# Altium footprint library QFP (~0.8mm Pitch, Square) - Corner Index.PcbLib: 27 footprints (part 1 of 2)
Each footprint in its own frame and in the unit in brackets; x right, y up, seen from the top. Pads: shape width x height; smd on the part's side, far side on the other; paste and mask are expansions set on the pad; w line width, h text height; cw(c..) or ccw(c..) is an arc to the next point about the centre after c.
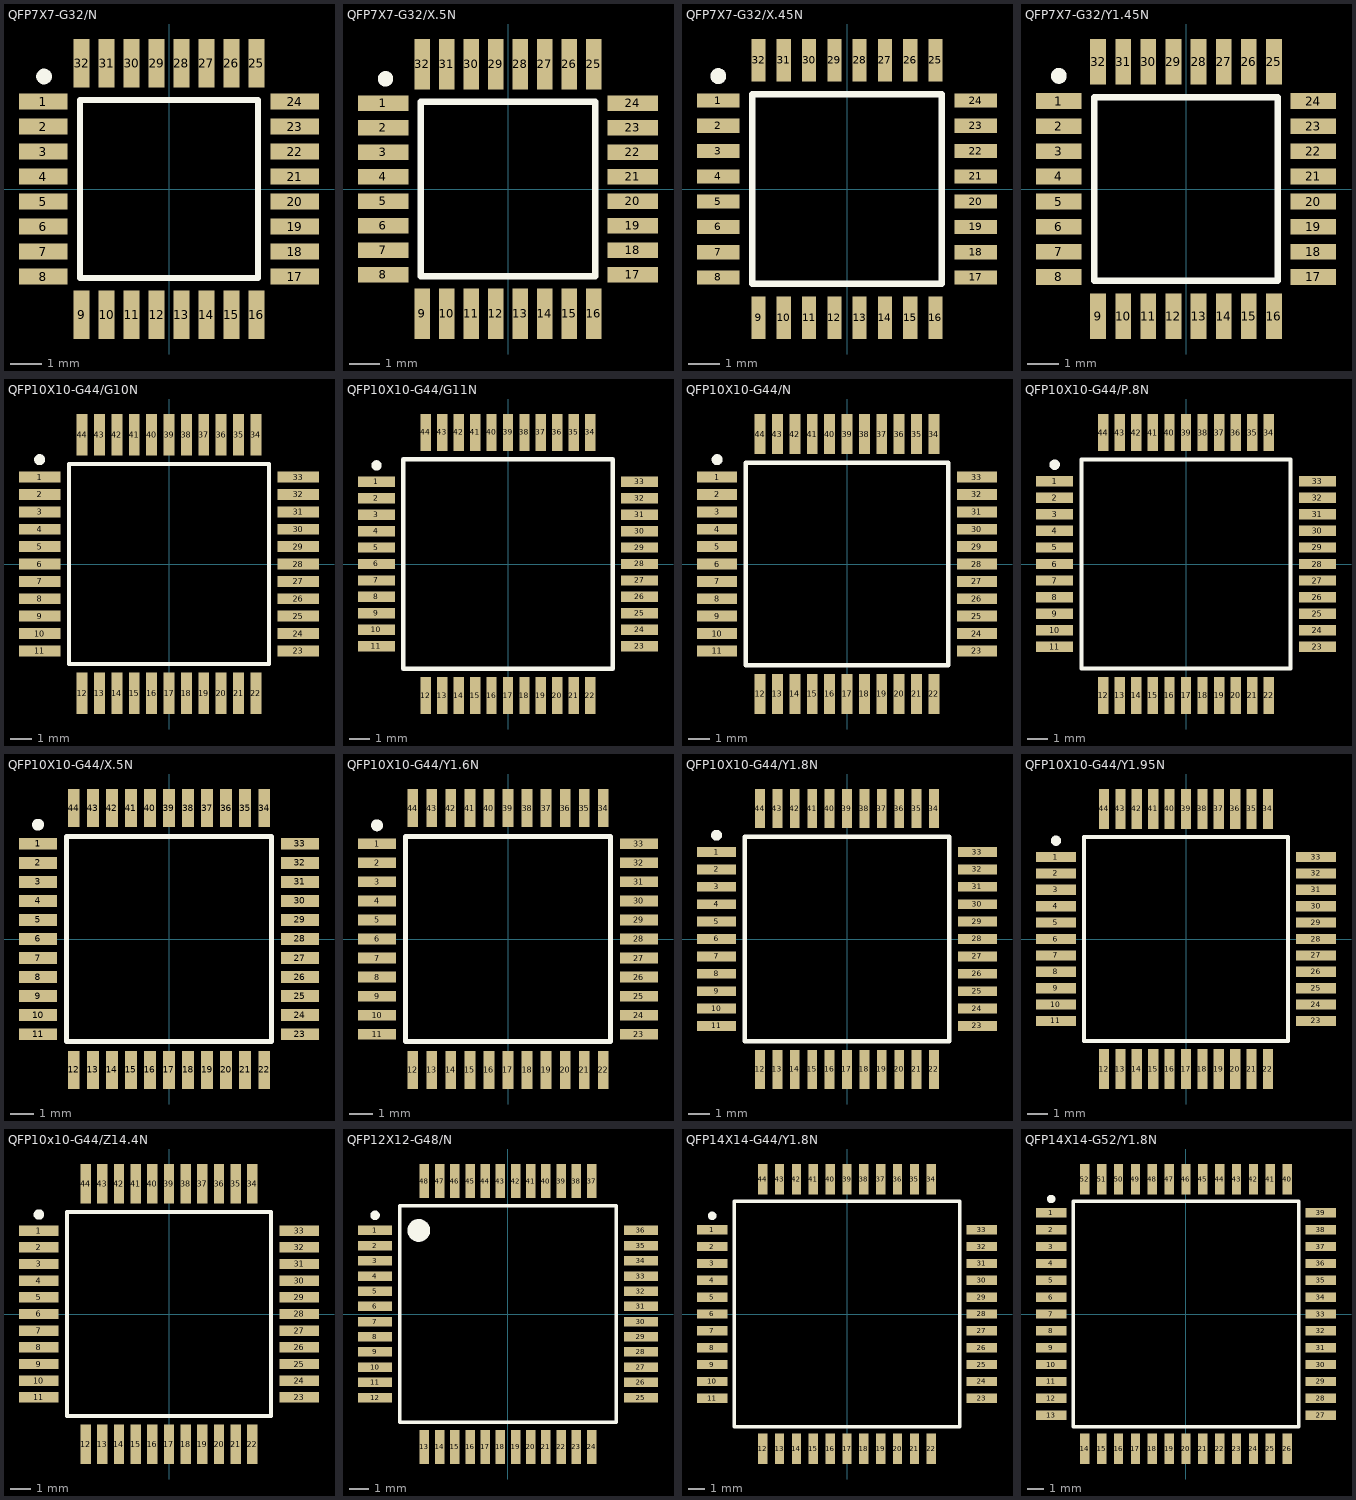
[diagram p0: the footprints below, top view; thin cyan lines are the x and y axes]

## QFP7X7-G32/N [mm]
pads (32):
  rect 1.55x0.5 smd: 1(-4.025,2.8) 2(-4.025,2) 3(-4.025,1.2) 4(-4.025,0.4) 5(-4.025,-0.4) 6(-4.025,-1.2) 7(-4.025,-2) 8(-4.025,-2.8) 17(4.025,-2.8) 18(4.025,-2) 19(4.025,-1.2) 20(4.025,-0.4) 21(4.025,0.4) 22(4.025,1.2) 23(4.025,2) 24(4.025,2.8)
  rect 0.5x1.55 smd: 9(-2.8,-4.025) 10(-2,-4.025) 11(-1.2,-4.025) 12(-0.4,-4.025) 13(0.4,-4.025) 14(1.2,-4.025) 15(2,-4.025) 16(2.8,-4.025) 25(2.8,4.025) 26(2,4.025) 27(1.2,4.025) 28(0.4,4.025) 29(-0.4,4.025) 30(-1.2,4.025) 31(-2,4.025) 32(-2.8,4.025)
Top Overlay:
  circle w0.25: c-4,3.6 r0.125
  lines w0.2: -2.85,-2.85 -2.85,2.85 2.85,2.85 2.85,-2.85 -2.85,-2.85

## QFP7X7-G32/X.5N [mm]
pads (32):
  rect 1.65x0.5 smd: 1(-4.075,2.8) 2(-4.075,2) 3(-4.075,1.2) 4(-4.075,0.4) 5(-4.075,-0.4) 6(-4.075,-1.2) 7(-4.075,-2) 8(-4.075,-2.8) 17(4.075,-2.8) 18(4.075,-2) 19(4.075,-1.2) 20(4.075,-0.4) 21(4.075,0.4) 22(4.075,1.2) 23(4.075,2) 24(4.075,2.8)
  rect 0.5x1.65 smd: 9(-2.8,-4.075) 10(-2,-4.075) 11(-1.2,-4.075) 12(-0.4,-4.075) 13(0.4,-4.075) 14(1.2,-4.075) 15(2,-4.075) 16(2.8,-4.075) 25(2.8,4.075) 26(2,4.075) 27(1.2,4.075) 28(0.4,4.075) 29(-0.4,4.075) 30(-1.2,4.075) 31(-2,4.075) 32(-2.8,4.075)
Top Overlay:
  circle w0.25: c-4,3.6 r0.125
  lines w0.2: -2.85,-2.85 -2.85,2.85 2.85,2.85 2.85,-2.85 -2.85,-2.85

## QFP7X7-G32/X.45N [mm]
pads (32):
  rect 1.35x0.45 smd: 1(-4.075,2.8) 2(-4.075,2) 3(-4.075,1.2) 4(-4.075,0.4) 5(-4.075,-0.4) 6(-4.075,-1.2) 7(-4.075,-2) 8(-4.075,-2.8) 17(4.075,-2.8) 18(4.075,-2) 19(4.075,-1.2) 20(4.075,-0.4) 21(4.075,0.4) 22(4.075,1.2) 23(4.075,2) 24(4.075,2.8)
  rect 0.45x1.35 smd: 9(-2.8,-4.075) 10(-2,-4.075) 11(-1.2,-4.075) 12(-0.4,-4.075) 13(0.4,-4.075) 14(1.2,-4.075) 15(2,-4.075) 16(2.8,-4.075) 25(2.8,4.075) 26(2,4.075) 27(1.2,4.075) 28(0.4,4.075) 29(-0.4,4.075) 30(-1.2,4.075) 31(-2,4.075) 32(-2.8,4.075)
Top Overlay:
  circle w0.25: c-4.075,3.575 r0.125
  lines w0.2: -3,-3 3,-3 3,3 -3,3 -3,-3

## QFP7X7-G32/Y1.45N [mm]
pads (32):
  rect 1.45x0.5 smd: 1(-4.05,2.8) 2(-4.05,2) 3(-4.05,1.2) 4(-4.05,0.4) 5(-4.05,-0.4) 6(-4.05,-1.2) 7(-4.05,-2) 8(-4.05,-2.8) 17(4.05,-2.8) 18(4.05,-2) 19(4.05,-1.2) 20(4.05,-0.4) 21(4.05,0.4) 22(4.05,1.2) 23(4.05,2) 24(4.05,2.8)
  rect 0.5x1.45 smd: 9(-2.8,-4.05) 10(-2,-4.05) 11(-1.2,-4.05) 12(-0.4,-4.05) 13(0.4,-4.05) 14(1.2,-4.05) 15(2,-4.05) 16(2.8,-4.05) 25(2.8,4.05) 26(2,4.05) 27(1.2,4.05) 28(0.4,4.05) 29(-0.4,4.05) 30(-1.2,4.05) 31(-2,4.05) 32(-2.8,4.05)
Top Overlay:
  circle w0.25: c-4.05,3.6 r0.125
  lines w0.2: -2.925,-2.925 -2.925,2.925 2.925,2.925 2.925,-2.925 -2.925,-2.925

## QFP10X10-G44/G10N [mm]
pads (44):
  rect 1.9x0.5 smd: 1(-5.95,4) 2(-5.95,3.2) 3(-5.95,2.4) 4(-5.95,1.6) 5(-5.95,0.8) 6(-5.95,0) 7(-5.95,-0.8) 8(-5.95,-1.6) 9(-5.95,-2.4) 10(-5.95,-3.2) 11(-5.95,-4) 23(5.95,-4) 24(5.95,-3.2) 25(5.95,-2.4) 26(5.95,-1.6) 27(5.95,-0.8) 28(5.95,0) 29(5.95,0.8) 30(5.95,1.6) 31(5.95,2.4) 32(5.95,3.2) 33(5.95,4)
  rect 0.5x1.9 smd: 12(-4,-5.95) 13(-3.2,-5.95) 14(-2.4,-5.95) 15(-1.6,-5.95) 16(-0.8,-5.95) 17(0,-5.95) 18(0.8,-5.95) 19(1.6,-5.95) 20(2.4,-5.95) 21(3.2,-5.95) 22(4,-5.95) 34(4,5.95) 35(3.2,5.95) 36(2.4,5.95) 37(1.6,5.95) 38(0.8,5.95) 39(0,5.95) 40(-0.8,5.95) 41(-1.6,5.95) 42(-2.4,5.95) 43(-3.2,5.95) 44(-4,5.95)
Top Overlay:
  circle w0.25: c-5.95,4.8 r0.125
  lines w0.2: -4.6,-4.6 4.6,-4.6 4.6,4.6 -4.6,4.6 -4.6,-4.6

## QFP10X10-G44/G11N [mm]
pads (44):
  rect 1.8x0.5 smd: 1(-6.4,4) 2(-6.4,3.2) 3(-6.4,2.4) 4(-6.4,1.6) 5(-6.4,0.8) 6(-6.4,0) 7(-6.4,-0.8) 8(-6.4,-1.6) 9(-6.4,-2.4) 10(-6.4,-3.2) 11(-6.4,-4) 23(6.4,-4) 24(6.4,-3.2) 25(6.4,-2.4) 26(6.4,-1.6) 27(6.4,-0.8) 28(6.4,0) 29(6.4,0.8) 30(6.4,1.6) 31(6.4,2.4) 32(6.4,3.2) 33(6.4,4)
  rect 0.5x1.8 smd: 12(-4,-6.4) 13(-3.2,-6.4) 14(-2.4,-6.4) 15(-1.6,-6.4) 16(-0.8,-6.4) 17(0,-6.4) 18(0.8,-6.4) 19(1.6,-6.4) 20(2.4,-6.4) 21(3.2,-6.4) 22(4,-6.4) 34(4,6.4) 35(3.2,6.4) 36(2.4,6.4) 37(1.6,6.4) 38(0.8,6.4) 39(0,6.4) 40(-0.8,6.4) 41(-1.6,6.4) 42(-2.4,6.4) 43(-3.2,6.4) 44(-4,6.4)
Top Overlay:
  circle w0.25: c-6.4,4.8 r0.125
  lines w0.2: -5.1,-5.1 5.1,-5.1 5.1,5.1 -5.1,5.1 -5.1,-5.1

## QFP10X10-G44/N [mm]
pads (44):
  rect 1.85x0.5 smd: 1(-5.975,4) 2(-5.975,3.2) 3(-5.975,2.4) 4(-5.975,1.6) 5(-5.975,0.8) 6(-5.975,0) 7(-5.975,-0.8) 8(-5.975,-1.6) 9(-5.975,-2.4) 10(-5.975,-3.2) 11(-5.975,-4) 23(5.975,-4) 24(5.975,-3.2) 25(5.975,-2.4) 26(5.975,-1.6) 27(5.975,-0.8) 28(5.975,0) 29(5.975,0.8) 30(5.975,1.6) 31(5.975,2.4) 32(5.975,3.2) 33(5.975,4)
  rect 0.5x1.85 smd: 12(-4,-5.975) 13(-3.2,-5.975) 14(-2.4,-5.975) 15(-1.6,-5.975) 16(-0.8,-5.975) 17(0,-5.975) 18(0.8,-5.975) 19(1.6,-5.975) 20(2.4,-5.975) 21(3.2,-5.975) 22(4,-5.975) 34(4,5.975) 35(3.2,5.975) 36(2.4,5.975) 37(1.6,5.975) 38(0.8,5.975) 39(0,5.975) 40(-0.8,5.975) 41(-1.6,5.975) 42(-2.4,5.975) 43(-3.2,5.975) 44(-4,5.975)
Top Overlay:
  circle w0.25: c-5.975,4.8 r0.125
  lines w0.2: -4.65,-4.65 4.65,-4.65 4.65,4.65 -4.65,4.65 -4.65,-4.65

## QFP10X10-G44/P.8N [mm]
pads (44):
  rect 1.8x0.5 smd: 1(-6.35,4) 2(-6.35,3.2) 3(-6.35,2.4) 4(-6.35,1.6) 5(-6.35,0.8) 6(-6.35,0) 7(-6.35,-0.8) 8(-6.35,-1.6) 9(-6.35,-2.4) 10(-6.35,-3.2) 11(-6.35,-4) 23(6.35,-4) 24(6.35,-3.2) 25(6.35,-2.4) 26(6.35,-1.6) 27(6.35,-0.8) 28(6.35,0) 29(6.35,0.8) 30(6.35,1.6) 31(6.35,2.4) 32(6.35,3.2) 33(6.35,4)
  rect 0.5x1.8 smd: 12(-4,-6.35) 13(-3.2,-6.35) 14(-2.4,-6.35) 15(-1.6,-6.35) 16(-0.8,-6.35) 17(0,-6.35) 18(0.8,-6.35) 19(1.6,-6.35) 20(2.4,-6.35) 21(3.2,-6.35) 22(4,-6.35) 34(4,6.35) 35(3.2,6.35) 36(2.4,6.35) 37(1.6,6.35) 38(0.8,6.35) 39(0,6.35) 40(-0.8,6.35) 41(-1.6,6.35) 42(-2.4,6.35) 43(-3.2,6.35) 44(-4,6.35)
Top Overlay:
  circle w0.25: c-6.35,4.8 r0.125
  lines w0.2: -5.05,-5.05 -5.05,5.05 5.05,5.05 5.05,-5.05 -5.05,-5.05

## QFP10X10-G44/X.5N [mm]
pads (44):
  rect 1.6x0.5 smd: 1(-5.5,4) 2(-5.5,3.2) 3(-5.5,2.4) 4(-5.5,1.6) 5(-5.5,0.8) 6(-5.5,0) 7(-5.5,-0.8) 8(-5.5,-1.6) 9(-5.5,-2.4) 10(-5.5,-3.2) 11(-5.5,-4) 23(5.5,-4) 24(5.5,-3.2) 25(5.5,-2.4) 26(5.5,-1.6) 27(5.5,-0.8) 28(5.5,0) 29(5.5,0.8) 30(5.5,1.6) 31(5.5,2.4) 32(5.5,3.2) 33(5.5,4)
  rect 0.5x1.6 smd: 12(-4,-5.5) 13(-3.2,-5.5) 14(-2.4,-5.5) 15(-1.6,-5.5) 16(-0.8,-5.5) 17(0,-5.5) 18(0.8,-5.5) 19(1.6,-5.5) 20(2.4,-5.5) 21(3.2,-5.5) 22(4,-5.5) 34(4,5.5) 35(3.2,5.5) 36(2.4,5.5) 37(1.6,5.5) 38(0.8,5.5) 39(0,5.5) 40(-0.8,5.5) 41(-1.6,5.5) 42(-2.4,5.5) 43(-3.2,5.5) 44(-4,5.5)
Top Overlay:
  circle w0.25: c-5.5,4.8 r0.125
  lines w0.2: -4.3,-4.3 4.3,-4.3 4.3,4.3 -4.3,4.3 -4.3,-4.3

## QFP10X10-G44/Y1.6N [mm]
pads (44):
  rect 1.6x0.45 smd: 1(-5.5,4) 2(-5.5,3.2) 3(-5.5,2.4) 4(-5.5,1.6) 5(-5.5,0.8) 6(-5.5,0) 7(-5.5,-0.8) 8(-5.5,-1.6) 9(-5.5,-2.4) 10(-5.5,-3.2) 11(-5.5,-4) 23(5.5,-4) 24(5.5,-3.2) 25(5.5,-2.4) 26(5.5,-1.6) 27(5.5,-0.8) 28(5.5,0) 29(5.5,0.8) 30(5.5,1.6) 31(5.5,2.4) 32(5.5,3.2) 33(5.5,4)
  rect 0.45x1.6 smd: 12(-4,-5.5) 13(-3.2,-5.5) 14(-2.4,-5.5) 15(-1.6,-5.5) 16(-0.8,-5.5) 17(0,-5.5) 18(0.8,-5.5) 19(1.6,-5.5) 20(2.4,-5.5) 21(3.2,-5.5) 22(4,-5.5) 34(4,5.5) 35(3.2,5.5) 36(2.4,5.5) 37(1.6,5.5) 38(0.8,5.5) 39(0,5.5) 40(-0.8,5.5) 41(-1.6,5.5) 42(-2.4,5.5) 43(-3.2,5.5) 44(-4,5.5)
Top Overlay:
  circle w0.25: c-5.5,4.775 r0.125
  lines w0.2: -4.3,-4.3 -4.3,4.3 4.3,4.3 4.3,-4.3 -4.3,-4.3

## QFP10X10-G44/Y1.8N [mm]
pads (44):
  rect 1.8x0.45 smd: 1(-6,4) 2(-6,3.2) 3(-6,2.4) 4(-6,1.6) 5(-6,0.8) 6(-6,0) 7(-6,-0.8) 8(-6,-1.6) 9(-6,-2.4) 10(-6,-3.2) 11(-6,-4) 23(6,-4) 24(6,-3.2) 25(6,-2.4) 26(6,-1.6) 27(6,-0.8) 28(6,0) 29(6,0.8) 30(6,1.6) 31(6,2.4) 32(6,3.2) 33(6,4)
  rect 0.45x1.8 smd: 12(-4,-6) 13(-3.2,-6) 14(-2.4,-6) 15(-1.6,-6) 16(-0.8,-6) 17(0,-6) 18(0.8,-6) 19(1.6,-6) 20(2.4,-6) 21(3.2,-6) 22(4,-6) 34(4,6) 35(3.2,6) 36(2.4,6) 37(1.6,6) 38(0.8,6) 39(0,6) 40(-0.8,6) 41(-1.6,6) 42(-2.4,6) 43(-3.2,6) 44(-4,6)
Top Overlay:
  circle w0.25: c-6,4.775 r0.125
  lines w0.2: -4.7,-4.7 4.7,-4.7 4.7,4.7 -4.7,4.7 -4.7,-4.7

## QFP10X10-G44/Y1.95N [mm]
pads (44):
  rect 1.95x0.5 smd: 1(-6.35,4) 2(-6.35,3.2) 3(-6.35,2.4) 4(-6.35,1.6) 5(-6.35,0.8) 6(-6.35,0) 7(-6.35,-0.8) 8(-6.35,-1.6) 9(-6.35,-2.4) 10(-6.35,-3.2) 11(-6.35,-4) 23(6.35,-4) 24(6.35,-3.2) 25(6.35,-2.4) 26(6.35,-1.6) 27(6.35,-0.8) 28(6.35,0) 29(6.35,0.8) 30(6.35,1.6) 31(6.35,2.4) 32(6.35,3.2) 33(6.35,4)
  rect 0.5x1.95 smd: 12(-4,-6.35) 13(-3.2,-6.35) 14(-2.4,-6.35) 15(-1.6,-6.35) 16(-0.8,-6.35) 17(0,-6.35) 18(0.8,-6.35) 19(1.6,-6.35) 20(2.4,-6.35) 21(3.2,-6.35) 22(4,-6.35) 34(4,6.35) 35(3.2,6.35) 36(2.4,6.35) 37(1.6,6.35) 38(0.8,6.35) 39(0,6.35) 40(-0.8,6.35) 41(-1.6,6.35) 42(-2.4,6.35) 43(-3.2,6.35) 44(-4,6.35)
Top Overlay:
  circle w0.25: c-6.35,4.8 r0.125
  lines w0.2: -4.975,-4.975 4.975,-4.975 4.975,4.975 -4.975,4.975 -4.975,-4.975

## QFP10x10-G44/Z14.4N [mm]
pads (44):
  rect 1.9x0.5 smd: 1(-6.25,4) 2(-6.25,3.2) 3(-6.25,2.4) 4(-6.25,1.6) 5(-6.25,0.8) 6(-6.25,0) 7(-6.25,-0.8) 8(-6.25,-1.6) 9(-6.25,-2.4) 10(-6.25,-3.2) 11(-6.25,-4) 23(6.25,-4) 24(6.25,-3.2) 25(6.25,-2.4) 26(6.25,-1.6) 27(6.25,-0.8) 28(6.25,0) 29(6.25,0.8) 30(6.25,1.6) 31(6.25,2.4) 32(6.25,3.2) 33(6.25,4)
  rect 0.5x1.9 smd: 12(-4,-6.25) 13(-3.2,-6.25) 14(-2.4,-6.25) 15(-1.6,-6.25) 16(-0.8,-6.25) 17(0,-6.25) 18(0.8,-6.25) 19(1.6,-6.25) 20(2.4,-6.25) 21(3.2,-6.25) 22(4,-6.25) 34(4,6.25) 35(3.2,6.25) 36(2.4,6.25) 37(1.6,6.25) 38(0.8,6.25) 39(0,6.25) 40(-0.8,6.25) 41(-1.6,6.25) 42(-2.4,6.25) 43(-3.2,6.25) 44(-4,6.25)
Top Overlay:
  circle w0.25: c-6.25,4.775 r0.125
  lines w0.2: -4.9,-4.9 -4.9,4.9 4.9,4.9 4.9,-4.9 -4.9,-4.9

## QFP12X12-G48/N [mm]
pads (48):
  rect 1.8x0.5 smd: 1(-7,4.4) 2(-7,3.6) 3(-7,2.8) 4(-7,2) 5(-7,1.2) 6(-7,0.4) 7(-7,-0.4) 8(-7,-1.2) 9(-7,-2) 10(-7,-2.8) 11(-7,-3.6) 12(-7,-4.4) 25(7,-4.4) 26(7,-3.6) 27(7,-2.8) 28(7,-2) 29(7,-1.2) 30(7,-0.4) 31(7,0.4) 32(7,1.2) 33(7,2) 34(7,2.8) 35(7,3.6) 36(7,4.4)
  rect 0.5x1.8 smd: 13(-4.4,-7) 14(-3.6,-7) 15(-2.8,-7) 16(-2,-7) 17(-1.2,-7) 18(-0.4,-7) 19(0.4,-7) 20(1.2,-7) 21(2,-7) 22(2.8,-7) 23(3.6,-7) 24(4.4,-7) 37(4.4,7) 38(3.6,7) 39(2.8,7) 40(2,7) 41(1.2,7) 42(0.4,7) 43(-0.4,7) 44(-1.2,7) 45(-2,7) 46(-2.8,7) 47(-3.6,7) 48(-4.4,7)
Top Overlay:
  circle w0.25: c-7,5.2 r0.125
  circle w0.6: c-4.7,4.4 r0.3
  lines w0.2: -5.7,-5.7 5.7,-5.7 5.7,5.7 -5.7,5.7 -5.7,-5.7

## QFP14X14-G44/Y1.8N [mm]
pads (44):
  rect 1.8x0.55 smd: 1(-8,5) 2(-8,4) 3(-8,3) 4(-8,2) 5(-8,1) 6(-8,0) 7(-8,-1) 8(-8,-2) 9(-8,-3) 10(-8,-4) 11(-8,-5) 23(8,-5) 24(8,-4) 25(8,-3) 26(8,-2) 27(8,-1) 28(8,0) 29(8,1) 30(8,2) 31(8,3) 32(8,4) 33(8,5)
  rect 0.55x1.8 smd: 12(-5,-8) 13(-4,-8) 14(-3,-8) 15(-2,-8) 16(-1,-8) 17(0,-8) 18(1,-8) 19(2,-8) 20(3,-8) 21(4,-8) 22(5,-8) 34(5,8) 35(4,8) 36(3,8) 37(2,8) 38(1,8) 39(0,8) 40(-1,8) 41(-2,8) 42(-3,8) 43(-4,8) 44(-5,8)
Top Overlay:
  circle w0.25: c-8,5.825 r0.125
  lines w0.2: -6.7,-6.7 6.7,-6.7 6.7,6.7 -6.7,6.7 -6.7,-6.7

## QFP14X14-G52/Y1.8N [mm]
pads (52):
  rect 1.8x0.55 smd: 1(-8,6) 2(-8,5) 3(-8,4) 4(-8,3) 5(-8,2) 6(-8,1) 7(-8,0) 8(-8,-1) 9(-8,-2) 10(-8,-3) 11(-8,-4) 12(-8,-5) 13(-8,-6) 27(8,-6) 28(8,-5) 29(8,-4) 30(8,-3) 31(8,-2) 32(8,-1) 33(8,0) 34(8,1) 35(8,2) 36(8,3) 37(8,4) 38(8,5) 39(8,6)
  rect 0.55x1.8 smd: 14(-6,-8) 15(-5,-8) 16(-4,-8) 17(-3,-8) 18(-2,-8) 19(-1,-8) 20(0,-8) 21(1,-8) 22(2,-8) 23(3,-8) 24(4,-8) 25(5,-8) 26(6,-8) 40(6,8) 41(5,8) 42(4,8) 43(3,8) 44(2,8) 45(1,8) 46(0,8) 47(-1,8) 48(-2,8) 49(-3,8) 50(-4,8) 51(-5,8) 52(-6,8)
Top Overlay:
  circle w0.25: c-8,6.825 r0.125
  lines w0.2: -6.7,-6.7 6.7,-6.7 6.7,6.7 -6.7,6.7 -6.7,-6.7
